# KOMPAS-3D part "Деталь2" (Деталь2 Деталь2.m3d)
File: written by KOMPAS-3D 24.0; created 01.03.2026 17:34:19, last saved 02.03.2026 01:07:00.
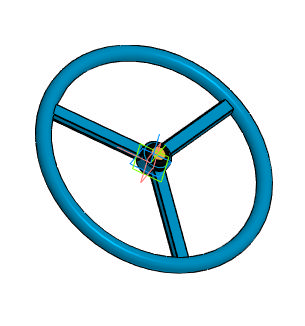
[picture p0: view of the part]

Document properties: Автор: R2D2; Полное имя файла: E:\Работа\Зайцев\GVWR3131M-2W-F-S Задвижка клиновая с выдвижным штоком DN.ru Ду50-200 Ру63\DN150\исходные материалы\Деталь2 Деталь2.m3d

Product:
- Body: Твердое тело1  | qty 1
    Масса: 4.922929
- Part/product: Деталь2
    Масса: 4.922929
    additional columns: Типовые

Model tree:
1. Твердое тело1  (labels: Твердое тело1)
2. Эскиз:1
3. Элемент выдавливания:1
     Расстояние 1 = 100
4. Эскиз:2
5. Элемент вращения:1
     Угол 1 = 360
6. Элемент выдавливания:2  (with: Грань.Элемент выдавливания:1, Грань.Элемент вращения:1)
     Расстояние 2 = 117.966
7. Массив по концентрической сетке:1  (with: Элемент выдавливания:2)  (labels: Грань.Твердое тело1)  (3 pattern instances)
     Шаг 2 = 360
